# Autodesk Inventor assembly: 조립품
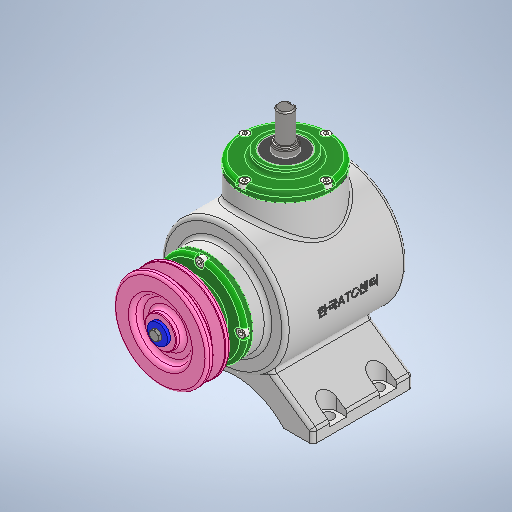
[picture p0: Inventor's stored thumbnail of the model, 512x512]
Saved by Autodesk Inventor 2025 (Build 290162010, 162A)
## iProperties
Created: 2024-07
Part Number: 조립품
Document SubType Name: Assembly
Designer: 계정
Author: 계정
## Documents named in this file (15)
- C:\Users\계정\Desktop\740709V1008\조립품.iam
- C:\Users\계정\Desktop\740709V1008\본체.ipt
- C:\Users\계정\Desktop\740709V1008\V-벨트풀리\V-벨트풀리.ipt
- C:\Users\계정\Desktop\740709V1008\메인 베벨기어\메인 베벨기어.ipt
- C:\Users\계정\Desktop\740709V1008\메인 축\메인 축.ipt
- C:\Users\계정\Desktop\740709V1008\베어링 6203\베어링 6203.ipt
- C:\Users\계정\Desktop\740709V1008\볼트 M4 x 10\볼트 M4 x 10.ipt
- C:\Users\계정\Desktop\740709V1008\서브 베벨기어\서브 베벨기어.ipt
- C:\Users\계정\Desktop\740709V1008\서브 축\서브 축.ipt
- C:\Users\계정\Desktop\740709V1008\오일실 17 x 32 x 8\오일실 17 x 32 x 8.ipt
- C:\Users\계정\Desktop\740709V1008\와셔 4 x 16\와셔 4 x 16.ipt
- C:\Users\계정\Desktop\740709V1008\육각볼트 M4 x 8\육각볼트 M4 x 8.ipt
- C:\Users\계정\Desktop\740709V1008\커버\커버.ipt
- C:\Users\계정\Desktop\740709V1008\키 4 x 4 x 14\키 4 x 4 x 14.ipt
- C:\Users\계정\Desktop\740709V1008\키 5 x 5 x 14\키 5 x 5 x 14.ipt
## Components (1 placed, 1 different names)
1. V-벨트풀리:1 — 각도:1
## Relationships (1: Angle 1)
- 각도:1 [Angle]: V-벨트풀리:1
